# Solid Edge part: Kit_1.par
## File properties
Sűrűség: 0,000 kg/m^3
Pontosság: 0,990
Author: ahadarics
Last saved by: ahadarics
Revision: 76
Username: ahadarics
Dokumentum tartalom típus: 0
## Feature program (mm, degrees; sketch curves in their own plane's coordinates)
base feature "unnamed BaseFeature 1"
sketch for "Furat_1" plane through (0, -45, 8.5) normal (0, 0, 1) x-axis (0, 1, 0)
  hole centre (0, 0) bore radius 2.067
hole "Furat_1" nominal diameter 5 finite  ThreadDepth = 4.5 mm
chamfer "Letörés_1" setback 0.5
thread "unnamed Thread 1"
chamfer "Letörés_2" setback 1
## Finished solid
Body 1: solid body, 48 faces, 52 edges, 6 vertices.
  Faces by surface: plane 16, cylinder 14, cone 11, torus 7
  Edges by curve: circle 45, line 6, intersection 1
Bounding box of the edges (mm; curved faces can reach further): 19.000 x 28.500 x 18.100, from (-9.5, -67.5, -9.5) to (9.5, -39, 8.6).
Cylindrical faces by radius (mm): R2.06 x1, R2.067 x1, R3.25 x2, R3.55 x1, R4.5 x1, R4.55 x1, R5.55 x1, R5.6 x1, R6.85 x1, R8 x2, R8.6 x1, R9.5 x1
Conical faces (half-angle, radius in mm at the cone's reference point): 8.8315 deg R4.75 x1, 15 deg R5.55 x1, 20.542 deg R3.55 x1, 24.3997 deg R3.55 x1, 27.3182 deg R3.0335 x1, 29.1112 deg R4.1553 x1, 45 deg R2.567 x1, 45 deg R4.65 x1, 45 deg R4.8 x1, 45 deg R8 x1, 60 deg R7.425 x1
Toroidal faces (ring radius, tube radius in mm): R3.2 r0.2 x1, R3.3 r0.3 x1, R4.3301 r0.2 x1, R4.35 r0.2 x1, R5.35 r0.2 x1, R5.4 r0.2 x2
Planar faces by outward normal: +y 5, +z 2, -y 9
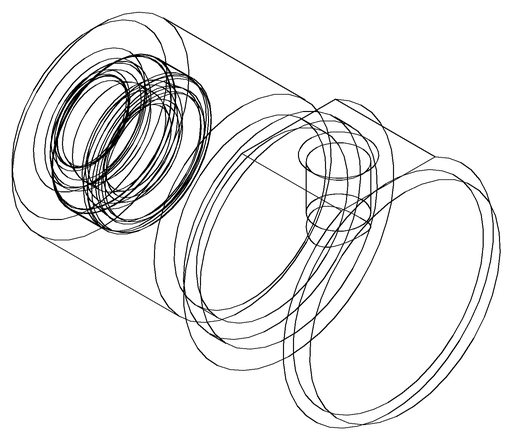
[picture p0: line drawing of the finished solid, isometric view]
